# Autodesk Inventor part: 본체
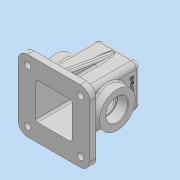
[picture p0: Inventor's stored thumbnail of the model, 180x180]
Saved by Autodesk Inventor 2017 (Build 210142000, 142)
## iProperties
Part Number: 본체
Material: 일반
Document SubType Name: Modeling
Designer: MRC
Density: 1 g/cm^3
Appearance: 기본값
Author: MRC
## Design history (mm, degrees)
sketch "스케치1"
  geometry: L1 (34, 34)-(-34, 34); L2 (-34, 34)-(-34, -34); L3 (-34, -34)-(34, -34); L4 (34, -34)-(34, 34); L5 (34, 34)-(-34, -34); L6 (-34, 34)-(34, -34); 1 further point
  constraints: 12 end point, 2 midpoint, 2 parallel, 1 horizontal, 1 perpendicular
  dimensions: "d0" = 68 distance of L3.end L2.end; "d1" = 68 distance of L2.end L1.end
extrude "돌출1" new body sketch "스케치1" stored distance "d2" = 105; taper "d3" = 0 deg
sketch "스케치2"
  geometry: L1 (34, 34)-(-34, 34) reference; L2 (-34, 34)-(-34, -34) reference; L3 (-34, -34)-(34, -34) reference; L4 (34, -34)-(34, 34) reference; L5 (57, 57)-(-57, 57); L6 (-57, 57)-(-57, -57); L7 (-57, -57)-(57, -57); L8 (57, -57)-(57, 57); L9 (57, 57)-(-57, -57); L10 (-57, 57)-(57, -57); 1 further point
  constraints: 12 end point, 2 midpoint, 2 parallel, 1 horizontal, 1 perpendicular
  dimensions: "d4" = 114 distance of L7.end L6.end; "d5" = 114 distance of L6.end L5.end
extrude "돌출2" join sketch "스케치2" distance "d6" = 10; taper "d7" = 0 deg
sketch "스케치3"
  geometry: L1 (91, -105)-(-23, -105) reference; C1 r 28.5 at (34, -53); 1 further point
  constraints: 1 centre point, 1 vertical alignment
  dimensions: "d8" = 57 diameter of C1; "d9" = 52 distance from line of L1 C1.centre
extrude "돌출3" join sketch "스케치3" distance "d10" = 15; taper "d11" = 0 deg
sketch "스케치4"
  geometry: C1 r 28.5 at (0, 0) reference; C2 r 17.5 at (0, 0); 1 further point
  constraints: 1 centre point, 1 concentric
  dimensions: "d12" = 35 diameter of C2
extrude "돌출4" cut sketch "스케치4" distance "d13" = 17; taper "d14" = 0 deg
sketch "스케치5"
  geometry: L1 (29, 29)-(-29, 29); L2 (-29, 29)-(-29, -29); L3 (-29, -29)-(29, -29); L4 (29, -29)-(29, 29); L5 (29, 29)-(-29, -29); L6 (-29, 29)-(29, -29); 1 further point
  constraints: 12 end point, 2 midpoint, 2 parallel, 1 horizontal, 1 perpendicular
  dimensions: "d15" = 58 distance of L3.end L2.end; "d16" = 58 distance of L2.end L1.end
extrude "돌출5" cut sketch "스케치5" distance "d17" = 100; taper "d18" = 0 deg
sketch "스케치6"
  geometry: C1 r 17.5 at (0, 0) reference; C2 r 15 at (0, 0); 1 further point
  constraints: 1 centre point, 1 concentric
  dimensions: "d19" = 30 diameter of C2
extrude "돌출6" cut sketch "스케치6" stored distance "d20" = 100; taper "d21" = 0 deg
sketch "스케치7"
  geometry: C1 r 20 at (0, 0); 1 further point
  constraints: 1 centre point, 1 coincident
  dimensions: "d22" = 40 diameter of C1
extrude "돌출7" join sketch "스케치7" distance "d23" = 10; taper "d24" = -8 deg
sketch "스케치8"
  geometry: C1 r 18.595 at (0, 0) reference; 1 further point
  constraints: 1 coincident
hole "구멍1" sketch "스케치8" at (0, 0) diameter "d25" = 22.835; stored, may be unused: countersink angle "d29" = 90 deg, drill point angle "d31" = 118 deg; dims "d26" = 15, "d27" = 4, "d28" = 2, "d30" = 15
sketch "스케치9"
  geometry: L1 (-42.5, -57)-(-42.5, 57) reference; L2 (-42.5, 49)-(42.569, 34); L3 (-52.5, 57)-(-42.5, 57) reference; L4 (52.5, 34)-(-42.5, 34) reference; 1 further point
  constraints: 2 end point, 2 point on line
  dimensions: "d32" = 8 distance from line of L3 L2.start; "d33" = 10 deg angle of L3 L2
feature "리브1" sketch "스케치9" dims "d34" = 1, "d35" = 10, "d36" = 0, "d37" = 0, "d38" = 1, "d39" = 1
fillet "모깎기1" dims "d53" = 8
fillet "모깎기2" dims "d54" = 8
fillet "모깎기3" dims "d55" = 3
fillet "모깎기4" dims "d56" = 3
fillet "모깎기5" dims "d57" = 3
fillet "모깎기6" dims "d58" = 3
fillet "모깎기7" dims "d59" = 15
sketch "스케치12"
  geometry: A1 r 15 centre (-42, 42) between (-42, 57) and (-57, 42) reference; A2 r 15 centre (-42, -42) between (-57, -42) and (-42, -57) reference; A3 r 15 centre (42, -42) between (42, -57) and (57, -42) reference; A4 r 15 centre (42, 42) between (57, 42) and (42, 57) reference; 5 further points
  constraints: 4 coincident
hole "구멍2" sketch "스케치12" at (42, -42), (-42, -42), (-42, 42), (42, 42) diameter "d60" = 10; stored, may be unused: countersink angle "d64" = 90 deg, drill point angle "d66" = 118 deg; dims "d61" = 15, "d62" = 18, "d63" = 2, "d65" = 15
fillet "모깎기8" dims "d67" = 0.3
fillet "모깎기9" dims "d68" = 3
chamfer "모따기1" distance "d69" = 1; stored, may be unused: second distance "d70" = 2, angle "d71" = 45 deg
sketch "스케치13"
  geometry: L1 (-8, 0)-(-8, -84) reference; L2 (7.405, 18)-(44.595, 18) reference; 2 further points
  constraints: 1 other
  dimensions: "d72" = 34 distance from line of point (26, -7) L1; "d73" = 25 distance from line of point (26, -7) L2
feature "엠보싱1" sketch "스케치13" dims "d0" = 68, "d1" = 68, "d74" = 0.5, "d75" = 0
fillet "모깎기10" dims "d76" = 3
fillet "모깎기11" dims "d77" = 3
node "솔리드1"
mirror "미러1"
mirror "미러2"
